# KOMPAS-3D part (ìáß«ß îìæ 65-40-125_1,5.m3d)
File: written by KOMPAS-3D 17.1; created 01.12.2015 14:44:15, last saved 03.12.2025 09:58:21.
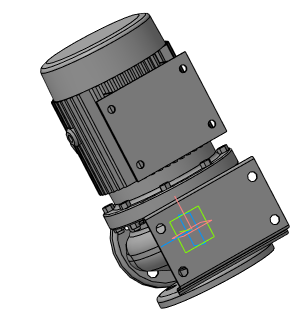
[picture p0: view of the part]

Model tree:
1. Операция без истории:5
